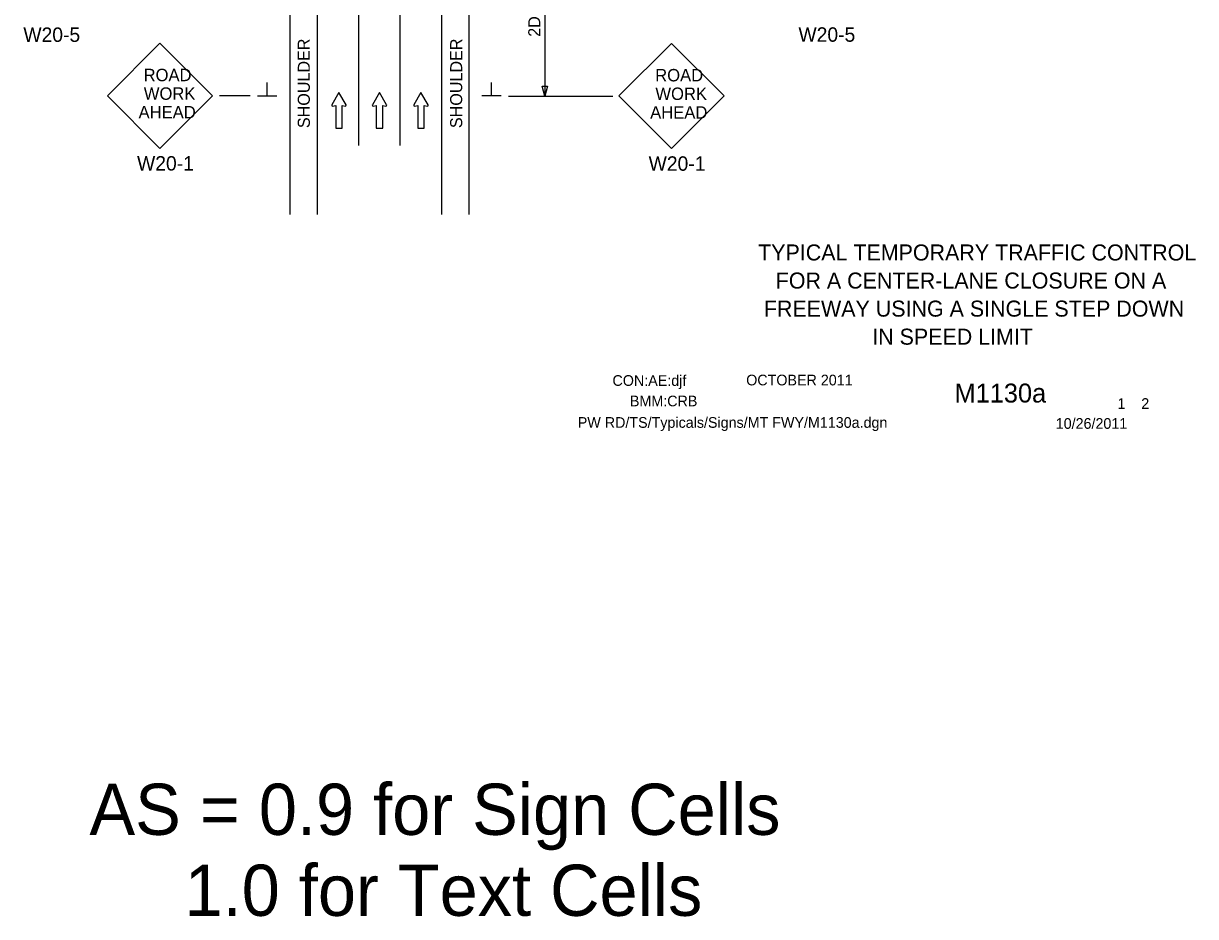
# Model space of a CAD drawing. Extents: x 16726 to 18482, y 5650 to 7013.
# Drawn here: x 16749 to 17429, y 5650 to 6168 of the extents above; entities that cross this region are included whole.
import ezdxf

# ---------------------------------------------------------------- set-up
doc = ezdxf.new("R2010")
doc.units = 0
for name, color, linetype in [('ALI_LEGAL_EX', 7, 'Continuous'), ('BORDER', 7, 'Continuous'), ('BORDER_SIGNAL_WO', 7, 'Continuous'), ('MT_SCRATCH_LEVEL_E', 7, 'Continuous'), ('PAVT_EDGE_EX', 7, 'Continuous'), ('TRAFFIC_SIGNS_PR', 7, 'Continuous'), ('TYPICAL_TEXT_DIMEN_PR', 7, 'Continuous')]:
    doc.layers.add(name, color=color, linetype=linetype)

msp = doc.modelspace()

# ---------------------------------------------------------------- linework, layer by layer
at = {"layer": 'ALI_LEGAL_EX'}
for p, q in [((16943.36, 6961.56), (16943.36, 6097.65)), ((16967.36, 6961.56), (16967.36, 6097.65))]:
    msp.add_line(p, q, dxfattribs=at)
for points in [[(16943.36, 6124.34), (16943.36, 6105.42)], [(16943.36, 6124.34), (16943.36, 6099.34)], [(16967.36, 6124.34), (16967.36, 6105.42)], [(16967.36, 6124.34), (16967.36, 6099.34)]]:
    msp.add_lwpolyline(points, dxfattribs=at)
at = {"layer": 'MT_SCRATCH_LEVEL_E'}
for p, q in [((16931.92, 6128.45), (16927.81, 6121.22)), ((16936.06, 6121.22), (16931.92, 6128.45)), ((16955.46, 6128.45), (16951.35, 6121.22)), ((16959.61, 6121.22), (16955.46, 6128.45)), ((16979.53, 6128.45), (16975.42, 6121.22)), ((16983.68, 6121.22), (16979.53, 6128.45)), ((16928.29, 6120.53), (16930.06, 6120.85)), ((16930.06, 6120.85), (16930.06, 6107.59)), ((16933.81, 6107.59), (16933.81, 6120.85)), ((16933.81, 6120.85), (16935.58, 6120.53)), ((16951.83, 6120.53), (16953.61, 6120.85)), ((16953.61, 6120.85), (16953.61, 6107.59)), ((16957.35, 6107.59), (16957.35, 6120.85)), ((16957.35, 6120.85), (16959.13, 6120.53)), ((16975.91, 6120.53), (16977.68, 6120.85)), ((16977.68, 6120.85), (16977.68, 6107.59)), ((16981.42, 6107.59), (16981.42, 6120.85)), ((16981.42, 6120.85), (16983.2, 6120.53)), ((16930.06, 6107.59), (16933.81, 6107.59)), ((16953.61, 6107.59), (16957.35, 6107.59)), ((16977.68, 6107.59), (16981.42, 6107.59))]:
    msp.add_line(p, q, dxfattribs=at)
for centre, start, end in [((16928.21, 6120.99), 150.42484, 279.96381), ((16935.65, 6120.99), 260.03619, 29.77312), ((16951.76, 6120.99), 150.42484, 279.96381), ((16959.2, 6120.99), 260.03619, 29.77312), ((16975.83, 6120.99), 150.42484, 279.96381), ((16983.27, 6120.99), 260.03619, 29.77312)]:
    msp.add_arc(centre, 0.463, start, end, dxfattribs=at)
at = {"layer": 'PAVT_EDGE_EX'}
for p, q in [((16903.36, 6926.44), (16903.36, 6057.56)), ((16919.36, 6926.44), (16919.36, 6057.56)), ((16991.36, 6926.44), (16991.36, 6057.56)), ((17007.36, 6926.44), (17007.36, 6057.56))]:
    msp.add_line(p, q, dxfattribs=at)
at = {"layer": 'TRAFFIC_SIGNS_PR'}
for p, q in [((16828.08, 6157.03), (16797.54, 6126.48)), ((16858.63, 6126.48), (16828.08, 6157.03)), ((17124.98, 6156.92), (17094.43, 6126.38)), ((17155.53, 6126.38), (17124.98, 6156.92)), ((16797.54, 6126.48), (16828.08, 6095.94)), ((16828.08, 6095.94), (16858.63, 6126.48)), ((17094.43, 6126.38), (17124.98, 6095.83)), ((17124.98, 6095.83), (17155.53, 6126.38))]:
    msp.add_line(p, q, dxfattribs=at)
at = {"layer": 'TYPICAL_TEXT_DIMEN_PR'}
for p, q in [((17051.36, 6201.26), (17051.36, 6126.26)), ((16890.23, 6126.41), (16890.23, 6134.2)), ((17020.48, 6126.41), (17020.48, 6134.2)), ((17051.36, 6126.26), (17049.79, 6132.12)), ((17049.79, 6132.12), (17051.36, 6132.12)), ((17051.36, 6132.12), (17052.93, 6132.12)), ((17052.93, 6132.12), (17051.36, 6126.26)), ((16880.36, 6126.41), (16862.65, 6126.41)), ((16884.61, 6126.41), (16895.86, 6126.41)), ((17026.11, 6126.41), (17014.86, 6126.41)), ((17030.36, 6126.26), (17090.92, 6126.26))]:
    msp.add_line(p, q, dxfattribs=at)

# ---------------------------------------------------------------- texts
at = {"layer": 'BORDER'}
for s, p in [('TYPICAL TEMPORARY TRAFFIC CONTROL', (17175.21, 6030.86)), ('FOR A CENTER-LANE CLOSURE ON A', (17185.42, 6014.56)), ('FREEWAY USING A SINGLE STEP DOWN', (17178.54, 5998.26)), ('IN SPEED LIMIT', (17241.42, 5981.96))]:
    msp.add_text(s, height=9.3, dxfattribs=at).set_placement(p)
at = {"layer": 'BORDER_SIGNAL_WO'}
for s, height, p in [('CON:AE:djf  ', 6.2, (17090.69, 5958.06)), ('    OCTOBER 2011    ', 6.2, (17159.08, 5958.34)), ('    M1130a   ', 11, (17272.86, 5948.38)), ('BMM:CRB   ', 6.2, (17100.81, 5946.17)), (' 1    2 ', 6.2, (17381.45, 5944.7)), ('PW RD/TS/Typicals/Signs/MT FWY/M1130a.dgn      ', 6.2, (17070.55, 5933.71)), ('10/26/2011    ', 6.2, (17347.93, 5933.13)), ('AS = 0.9 for Sign Cells', 29.7271, (16787.14, 5697.35)), ('     1.0 for Text Cells', 29.7271, (16787.14, 5650.34))]:
    msp.add_text(s, height=height, dxfattribs=at).set_placement(p)
at = {"layer": 'TRAFFIC_SIGNS_PR'}
for s, height, p in [('W20-5', 8.37, (16748.79, 6157.77)), ('W20-5', 8.37, (17198.62, 6157.86)), ('ROAD', 7.2, (16818.57, 6134.96)), ('ROAD', 7.2, (17115.47, 6134.85)), ('WORK', 7.2, (16818.69, 6124.16)), ('WORK', 7.2, (17115.59, 6124.05)), ('AHEAD', 7.2, (16815.66, 6113.36)), ('AHEAD', 7.2, (17112.56, 6113.25)), ('W20-1', 8.37, (16814.77, 6083.07)), ('W20-1', 8.37, (17111.67, 6082.96))]:
    msp.add_text(s, height=height, dxfattribs=at).set_placement(p)
at = {"layer": 'TYPICAL_TEXT_DIMEN_PR'}
for s, p in [('2D', (17048.8, 6160.73)), ('SHOULDER', (16915.04, 6107.71)), ('SHOULDER', (17003.47, 6107.71))]:
    msp.add_text(s, height=7, rotation=90, dxfattribs=at).set_placement(p)

doc.saveas('drawing.dxf')
